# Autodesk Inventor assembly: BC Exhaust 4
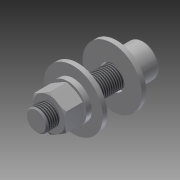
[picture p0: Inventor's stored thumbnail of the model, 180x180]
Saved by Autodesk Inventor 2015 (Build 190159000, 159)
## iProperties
Created: 2007-02
Part Number: BC Exhaust 4
Document SubType Name: Assembly
Designer: Autodesk, Inc.
Mass: 139.846 g
Surface Area: 109.169 cm^2
Volume: 17.7921 cm^3
Density: 7.86 g/cm^3
ClientObjectVersion: 1
Author: Autodesk, Inc.
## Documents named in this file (5)
- C:\Users\Public\Documents\Autodesk\Inventor 2015\Samples\Models\Assemblies\Blower\Blower\Design Accelerator\BC Exhaust 31.iam
- C:\Users\Public\Documents\Autodesk\Inventor 2015\Samples\Standard Parts\en-US\ANSI B18.22.1\ANSI B18.22.1 - 1_2 - wide - Type A.ipt
- C:\Users\Public\Documents\Autodesk\Inventor 2015\Samples\Standard Parts\en-US\ANSI B18.21.1\ANSI B18.21.1 - 0.5.ipt
- C:\Users\Public\Documents\Autodesk\Inventor 2015\Samples\Standard Parts\en-US\ANSI B18.3(13)\ANSI B18.3 - 1_2-20 UNF - 2(22).ipt
- C:\Users\Public\Documents\Autodesk\Inventor 2015\Samples\Standard Parts\en-US\ANSI B18.2.2(09)\ANSI B18.2.2 - 1_2 - 20(2).ipt
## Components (6 placed, 4 different names)
1. ANSI B18.22.1 - 1/2 - wide - Type A:1
2. ANSI B18.21.1 - 0.5:2
3. ANSI B18.3 - 1/2-20 UNF - 2:3
4. ANSI B18.22.1 - 1/2 - wide - Type A:4
5. ANSI B18.21.1 - 0.5:5
6. ANSI B18.2.2 - 1/2 - 20:6
